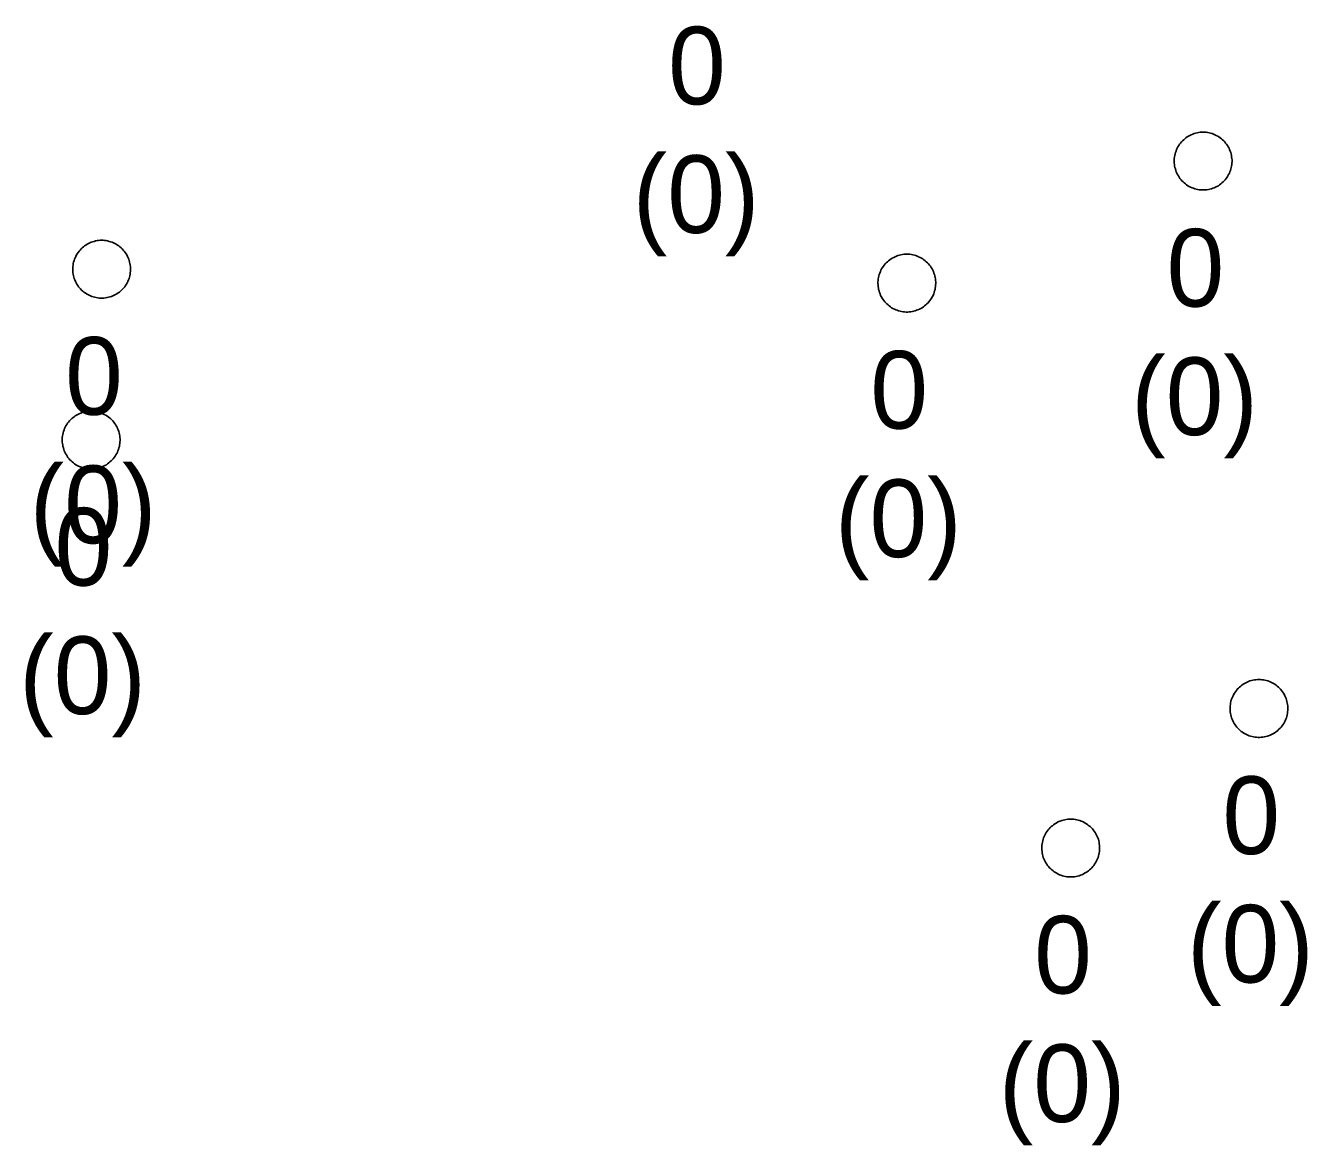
# Model space of a CAD drawing. Extents: x -606452 to -604459, y -1157823 to -1156972.
# Drawn here: x -605880.55 to -605869.47, y -1157244.86 to -1157235.18 of the extents above; entities that cross this region are included whole.
import ezdxf

# ---------------------------------------------------------------- set-up
doc = ezdxf.new("R2010")
doc.units = 0
doc.layers.add('Vstupní šachta stoky', color=7, linetype='Continuous')

msp = doc.modelspace()

# ---------------------------------------------------------------- linework, layer by layer
at = {"layer": 'Vstupní šachta stoky'}
for p, q in [((-605870.38, -1157236.102), (-605870.367, -1157236.102)), ((-605879.906, -1157237.037), (-605879.893, -1157237.037)), ((-605872.942, -1157237.157), (-605872.929, -1157237.157)), ((-605879.997, -1157238.514), (-605879.984, -1157238.514)), ((-605869.897, -1157240.835), (-605869.884, -1157240.835)), ((-605871.525, -1157242.041), (-605871.512, -1157242.041))]:
    msp.add_line(p, q, dxfattribs=at)
for points in [[(-605870.367, -1157236.102), (-605870.354, -1157236.102), (-605870.341, -1157236.103), (-605870.328, -1157236.105), (-605870.315, -1157236.108), (-605870.302, -1157236.111), (-605870.289, -1157236.114), (-605870.277, -1157236.119), (-605870.265, -1157236.124), (-605870.253, -1157236.13), (-605870.241, -1157236.136), (-605870.23, -1157236.143), (-605870.219, -1157236.151), (-605870.209, -1157236.159), (-605870.199, -1157236.167), (-605870.189, -1157236.176), (-605870.18, -1157236.186), (-605870.172, -1157236.196), (-605870.164, -1157236.207), (-605870.156, -1157236.218), (-605870.149, -1157236.229), (-605870.143, -1157236.241), (-605870.138, -1157236.253), (-605870.133, -1157236.265), (-605870.128, -1157236.277), (-605870.125, -1157236.29), (-605870.122, -1157236.303), (-605870.12, -1157236.316), (-605870.118, -1157236.329), (-605870.117, -1157236.342), (-605870.117, -1157236.355), (-605870.118, -1157236.369), (-605870.119, -1157236.382), (-605870.121, -1157236.395), (-605870.123, -1157236.408), (-605870.127, -1157236.42), (-605870.13, -1157236.433), (-605870.135, -1157236.445), (-605870.14, -1157236.458), (-605870.146, -1157236.469), (-605870.153, -1157236.481), (-605870.16, -1157236.492), (-605870.167, -1157236.503), (-605870.176, -1157236.513), (-605870.184, -1157236.523), (-605870.194, -1157236.532), (-605870.204, -1157236.541), (-605870.214, -1157236.55), (-605870.224, -1157236.557), (-605870.235, -1157236.565), (-605870.247, -1157236.571), (-605870.259, -1157236.577), (-605870.271, -1157236.583), (-605870.283, -1157236.587), (-605870.295, -1157236.592), (-605870.308, -1157236.595), (-605870.321, -1157236.598), (-605870.334, -1157236.6), (-605870.347, -1157236.601), (-605870.36, -1157236.602), (-605870.374, -1157236.602), (-605870.387, -1157236.601), (-605870.4, -1157236.6), (-605870.413, -1157236.598), (-605870.426, -1157236.595), (-605870.439, -1157236.592), (-605870.451, -1157236.587), (-605870.463, -1157236.583), (-605870.475, -1157236.577), (-605870.487, -1157236.571), (-605870.499, -1157236.565), (-605870.51, -1157236.557), (-605870.52, -1157236.55), (-605870.53, -1157236.541), (-605870.54, -1157236.532), (-605870.55, -1157236.523), (-605870.558, -1157236.513), (-605870.567, -1157236.503), (-605870.574, -1157236.492), (-605870.581, -1157236.481), (-605870.588, -1157236.469), (-605870.594, -1157236.458), (-605870.599, -1157236.445), (-605870.604, -1157236.433), (-605870.607, -1157236.42), (-605870.611, -1157236.408), (-605870.613, -1157236.395), (-605870.615, -1157236.382), (-605870.616, -1157236.369), (-605870.617, -1157236.355), (-605870.617, -1157236.342), (-605870.616, -1157236.329), (-605870.614, -1157236.316), (-605870.612, -1157236.303), (-605870.609, -1157236.29), (-605870.606, -1157236.277), (-605870.601, -1157236.265), (-605870.596, -1157236.253), (-605870.591, -1157236.241), (-605870.585, -1157236.229), (-605870.578, -1157236.218)], [(-605870.578, -1157236.218), (-605870.57, -1157236.207), (-605870.562, -1157236.196), (-605870.554, -1157236.186), (-605870.545, -1157236.176), (-605870.535, -1157236.167), (-605870.525, -1157236.159), (-605870.515, -1157236.151), (-605870.504, -1157236.143), (-605870.493, -1157236.136), (-605870.481, -1157236.13), (-605870.469, -1157236.124), (-605870.457, -1157236.119), (-605870.445, -1157236.114), (-605870.432, -1157236.111), (-605870.419, -1157236.108), (-605870.406, -1157236.105), (-605870.393, -1157236.103), (-605870.38, -1157236.102)], [(-605879.893, -1157237.037), (-605879.88, -1157237.037), (-605879.867, -1157237.038), (-605879.854, -1157237.04), (-605879.841, -1157237.043), (-605879.828, -1157237.046), (-605879.815, -1157237.049), (-605879.803, -1157237.054), (-605879.791, -1157237.059), (-605879.779, -1157237.065), (-605879.767, -1157237.071), (-605879.756, -1157237.078), (-605879.745, -1157237.086), (-605879.735, -1157237.094), (-605879.725, -1157237.102), (-605879.715, -1157237.111), (-605879.706, -1157237.121), (-605879.698, -1157237.131), (-605879.69, -1157237.142), (-605879.682, -1157237.153), (-605879.675, -1157237.164), (-605879.669, -1157237.176), (-605879.664, -1157237.188), (-605879.659, -1157237.2), (-605879.654, -1157237.212), (-605879.651, -1157237.225), (-605879.648, -1157237.238), (-605879.646, -1157237.251), (-605879.644, -1157237.264), (-605879.643, -1157237.277), (-605879.643, -1157237.29), (-605879.644, -1157237.304), (-605879.645, -1157237.317), (-605879.647, -1157237.33), (-605879.649, -1157237.343), (-605879.653, -1157237.355), (-605879.656, -1157237.368), (-605879.661, -1157237.38), (-605879.666, -1157237.393), (-605879.672, -1157237.404), (-605879.679, -1157237.416), (-605879.686, -1157237.427), (-605879.693, -1157237.438), (-605879.702, -1157237.448), (-605879.71, -1157237.458), (-605879.72, -1157237.467), (-605879.73, -1157237.476), (-605879.74, -1157237.485), (-605879.75, -1157237.492), (-605879.761, -1157237.5), (-605879.773, -1157237.506), (-605879.785, -1157237.512), (-605879.797, -1157237.518), (-605879.809, -1157237.522), (-605879.821, -1157237.527), (-605879.834, -1157237.53), (-605879.847, -1157237.533), (-605879.86, -1157237.535), (-605879.873, -1157237.536), (-605879.886, -1157237.537), (-605879.9, -1157237.537), (-605879.913, -1157237.536), (-605879.926, -1157237.535), (-605879.939, -1157237.533), (-605879.952, -1157237.53), (-605879.965, -1157237.527), (-605879.977, -1157237.522), (-605879.989, -1157237.518), (-605880.001, -1157237.512), (-605880.013, -1157237.506), (-605880.025, -1157237.5), (-605880.036, -1157237.492), (-605880.046, -1157237.485), (-605880.056, -1157237.476), (-605880.066, -1157237.467), (-605880.076, -1157237.458), (-605880.084, -1157237.448), (-605880.093, -1157237.438), (-605880.1, -1157237.427), (-605880.107, -1157237.416), (-605880.114, -1157237.404), (-605880.12, -1157237.393), (-605880.125, -1157237.38), (-605880.13, -1157237.368), (-605880.133, -1157237.355), (-605880.137, -1157237.343), (-605880.139, -1157237.33), (-605880.141, -1157237.317), (-605880.142, -1157237.304), (-605880.143, -1157237.29), (-605880.143, -1157237.277), (-605880.142, -1157237.264), (-605880.14, -1157237.251), (-605880.138, -1157237.238), (-605880.135, -1157237.225), (-605880.132, -1157237.212), (-605880.127, -1157237.2), (-605880.122, -1157237.188), (-605880.117, -1157237.176), (-605880.111, -1157237.164), (-605880.104, -1157237.153)], [(-605880.104, -1157237.153), (-605880.096, -1157237.142), (-605880.088, -1157237.131), (-605880.08, -1157237.121), (-605880.071, -1157237.111), (-605880.061, -1157237.102), (-605880.051, -1157237.094), (-605880.041, -1157237.086), (-605880.03, -1157237.078), (-605880.019, -1157237.071), (-605880.007, -1157237.065), (-605879.995, -1157237.059), (-605879.983, -1157237.054), (-605879.971, -1157237.049), (-605879.958, -1157237.046), (-605879.945, -1157237.043), (-605879.932, -1157237.04), (-605879.919, -1157237.038), (-605879.906, -1157237.037)], [(-605872.929, -1157237.157), (-605872.916, -1157237.157), (-605872.903, -1157237.158), (-605872.89, -1157237.16), (-605872.877, -1157237.163), (-605872.864, -1157237.166), (-605872.851, -1157237.169), (-605872.839, -1157237.174), (-605872.827, -1157237.179), (-605872.815, -1157237.185), (-605872.803, -1157237.191), (-605872.792, -1157237.198), (-605872.781, -1157237.206), (-605872.771, -1157237.214), (-605872.761, -1157237.222), (-605872.751, -1157237.231), (-605872.742, -1157237.241), (-605872.734, -1157237.251), (-605872.726, -1157237.262), (-605872.718, -1157237.273), (-605872.711, -1157237.284), (-605872.705, -1157237.296), (-605872.7, -1157237.308), (-605872.695, -1157237.32), (-605872.69, -1157237.332), (-605872.687, -1157237.345), (-605872.684, -1157237.358), (-605872.682, -1157237.371), (-605872.68, -1157237.384), (-605872.679, -1157237.397), (-605872.679, -1157237.41), (-605872.68, -1157237.424), (-605872.681, -1157237.437), (-605872.683, -1157237.45), (-605872.685, -1157237.463), (-605872.689, -1157237.475), (-605872.692, -1157237.488), (-605872.697, -1157237.5), (-605872.702, -1157237.513), (-605872.708, -1157237.524), (-605872.715, -1157237.536), (-605872.722, -1157237.547), (-605872.729, -1157237.558), (-605872.738, -1157237.568), (-605872.746, -1157237.578), (-605872.756, -1157237.587), (-605872.766, -1157237.596), (-605872.776, -1157237.605), (-605872.786, -1157237.612), (-605872.797, -1157237.62), (-605872.809, -1157237.626), (-605872.821, -1157237.632), (-605872.833, -1157237.638), (-605872.845, -1157237.642), (-605872.857, -1157237.647), (-605872.87, -1157237.65), (-605872.883, -1157237.653), (-605872.896, -1157237.655), (-605872.909, -1157237.656), (-605872.922, -1157237.657), (-605872.936, -1157237.657), (-605872.949, -1157237.656), (-605872.962, -1157237.655), (-605872.975, -1157237.653), (-605872.988, -1157237.65), (-605873.001, -1157237.647), (-605873.013, -1157237.642), (-605873.025, -1157237.638), (-605873.037, -1157237.632), (-605873.049, -1157237.626), (-605873.061, -1157237.62), (-605873.072, -1157237.612), (-605873.082, -1157237.605), (-605873.092, -1157237.596), (-605873.102, -1157237.587), (-605873.112, -1157237.578), (-605873.12, -1157237.568), (-605873.129, -1157237.558), (-605873.136, -1157237.547), (-605873.143, -1157237.536), (-605873.15, -1157237.524), (-605873.156, -1157237.513), (-605873.161, -1157237.5), (-605873.166, -1157237.488), (-605873.169, -1157237.475), (-605873.173, -1157237.463), (-605873.175, -1157237.45), (-605873.177, -1157237.437), (-605873.178, -1157237.424), (-605873.179, -1157237.41), (-605873.179, -1157237.397), (-605873.178, -1157237.384), (-605873.176, -1157237.371), (-605873.174, -1157237.358), (-605873.171, -1157237.345), (-605873.168, -1157237.332), (-605873.163, -1157237.32), (-605873.158, -1157237.308), (-605873.153, -1157237.296), (-605873.147, -1157237.284), (-605873.14, -1157237.273)], [(-605873.14, -1157237.273), (-605873.132, -1157237.262), (-605873.124, -1157237.251), (-605873.116, -1157237.241), (-605873.107, -1157237.231), (-605873.097, -1157237.222), (-605873.087, -1157237.214), (-605873.077, -1157237.206), (-605873.066, -1157237.198), (-605873.055, -1157237.191), (-605873.043, -1157237.185), (-605873.031, -1157237.179), (-605873.019, -1157237.174), (-605873.007, -1157237.169), (-605872.994, -1157237.166), (-605872.981, -1157237.163), (-605872.968, -1157237.16), (-605872.955, -1157237.158), (-605872.942, -1157237.157)], [(-605879.984, -1157238.514), (-605879.971, -1157238.514), (-605879.958, -1157238.515), (-605879.945, -1157238.517), (-605879.932, -1157238.52), (-605879.919, -1157238.523), (-605879.906, -1157238.526), (-605879.894, -1157238.531), (-605879.882, -1157238.536), (-605879.87, -1157238.542), (-605879.858, -1157238.548), (-605879.847, -1157238.555), (-605879.836, -1157238.563), (-605879.826, -1157238.571), (-605879.816, -1157238.579), (-605879.806, -1157238.588), (-605879.797, -1157238.598), (-605879.789, -1157238.608), (-605879.781, -1157238.619), (-605879.773, -1157238.63), (-605879.766, -1157238.641), (-605879.76, -1157238.653), (-605879.755, -1157238.665), (-605879.75, -1157238.677), (-605879.745, -1157238.689), (-605879.742, -1157238.702), (-605879.739, -1157238.715), (-605879.737, -1157238.728), (-605879.735, -1157238.741), (-605879.734, -1157238.754), (-605879.734, -1157238.767), (-605879.735, -1157238.781), (-605879.736, -1157238.794), (-605879.738, -1157238.807), (-605879.74, -1157238.82), (-605879.744, -1157238.832), (-605879.747, -1157238.845), (-605879.752, -1157238.857), (-605879.757, -1157238.87), (-605879.763, -1157238.881), (-605879.77, -1157238.893), (-605879.777, -1157238.904), (-605879.784, -1157238.915), (-605879.793, -1157238.925), (-605879.801, -1157238.935), (-605879.811, -1157238.944), (-605879.821, -1157238.953), (-605879.831, -1157238.962), (-605879.841, -1157238.969), (-605879.852, -1157238.977), (-605879.864, -1157238.983), (-605879.876, -1157238.989), (-605879.888, -1157238.995), (-605879.9, -1157238.999), (-605879.912, -1157239.004), (-605879.925, -1157239.007), (-605879.938, -1157239.01), (-605879.951, -1157239.012), (-605879.964, -1157239.013), (-605879.977, -1157239.014), (-605879.991, -1157239.014), (-605880.004, -1157239.013), (-605880.017, -1157239.012), (-605880.03, -1157239.01), (-605880.043, -1157239.007), (-605880.056, -1157239.004), (-605880.068, -1157238.999), (-605880.08, -1157238.995), (-605880.092, -1157238.989), (-605880.104, -1157238.983), (-605880.116, -1157238.977), (-605880.127, -1157238.969), (-605880.137, -1157238.962), (-605880.147, -1157238.953), (-605880.157, -1157238.944), (-605880.167, -1157238.935), (-605880.175, -1157238.925), (-605880.184, -1157238.915), (-605880.191, -1157238.904), (-605880.198, -1157238.893), (-605880.205, -1157238.881), (-605880.211, -1157238.87), (-605880.216, -1157238.857), (-605880.221, -1157238.845), (-605880.224, -1157238.832), (-605880.228, -1157238.82), (-605880.23, -1157238.807), (-605880.232, -1157238.794), (-605880.233, -1157238.781), (-605880.234, -1157238.767), (-605880.234, -1157238.754), (-605880.233, -1157238.741), (-605880.231, -1157238.728), (-605880.229, -1157238.715), (-605880.226, -1157238.702), (-605880.223, -1157238.689), (-605880.218, -1157238.677), (-605880.213, -1157238.665), (-605880.208, -1157238.653), (-605880.202, -1157238.641), (-605880.195, -1157238.63)], [(-605880.195, -1157238.63), (-605880.187, -1157238.619), (-605880.179, -1157238.608), (-605880.171, -1157238.598), (-605880.162, -1157238.588), (-605880.152, -1157238.579), (-605880.142, -1157238.571), (-605880.132, -1157238.563), (-605880.121, -1157238.555), (-605880.11, -1157238.548), (-605880.098, -1157238.542), (-605880.086, -1157238.536), (-605880.074, -1157238.531), (-605880.062, -1157238.526), (-605880.049, -1157238.523), (-605880.036, -1157238.52), (-605880.023, -1157238.517), (-605880.01, -1157238.515), (-605879.997, -1157238.514)], [(-605869.884, -1157240.835), (-605869.871, -1157240.835), (-605869.858, -1157240.836), (-605869.845, -1157240.838), (-605869.832, -1157240.841), (-605869.819, -1157240.844), (-605869.806, -1157240.847), (-605869.794, -1157240.852), (-605869.782, -1157240.857), (-605869.77, -1157240.863), (-605869.758, -1157240.869), (-605869.747, -1157240.876), (-605869.736, -1157240.884), (-605869.726, -1157240.892), (-605869.716, -1157240.9), (-605869.706, -1157240.909), (-605869.697, -1157240.919), (-605869.689, -1157240.929), (-605869.681, -1157240.94), (-605869.673, -1157240.951), (-605869.666, -1157240.962), (-605869.66, -1157240.974), (-605869.655, -1157240.986), (-605869.65, -1157240.998), (-605869.645, -1157241.01), (-605869.642, -1157241.023), (-605869.639, -1157241.036), (-605869.637, -1157241.049), (-605869.635, -1157241.062), (-605869.634, -1157241.075), (-605869.634, -1157241.088), (-605869.635, -1157241.102), (-605869.636, -1157241.115), (-605869.638, -1157241.128), (-605869.64, -1157241.141), (-605869.644, -1157241.153), (-605869.647, -1157241.166), (-605869.652, -1157241.178), (-605869.657, -1157241.191), (-605869.663, -1157241.202), (-605869.67, -1157241.214), (-605869.677, -1157241.225), (-605869.684, -1157241.236), (-605869.693, -1157241.246), (-605869.701, -1157241.256), (-605869.711, -1157241.265), (-605869.721, -1157241.274), (-605869.731, -1157241.283), (-605869.741, -1157241.29), (-605869.752, -1157241.298), (-605869.764, -1157241.304), (-605869.776, -1157241.31), (-605869.788, -1157241.316), (-605869.8, -1157241.32), (-605869.812, -1157241.325), (-605869.825, -1157241.328), (-605869.838, -1157241.331), (-605869.851, -1157241.333), (-605869.864, -1157241.334), (-605869.877, -1157241.335), (-605869.891, -1157241.335), (-605869.904, -1157241.334), (-605869.917, -1157241.333), (-605869.93, -1157241.331), (-605869.943, -1157241.328), (-605869.956, -1157241.325), (-605869.968, -1157241.32), (-605869.98, -1157241.316), (-605869.992, -1157241.31), (-605870.004, -1157241.304), (-605870.016, -1157241.298), (-605870.027, -1157241.29), (-605870.037, -1157241.283), (-605870.047, -1157241.274), (-605870.057, -1157241.265), (-605870.067, -1157241.256), (-605870.075, -1157241.246), (-605870.084, -1157241.236), (-605870.091, -1157241.225), (-605870.098, -1157241.214), (-605870.105, -1157241.202), (-605870.111, -1157241.191), (-605870.116, -1157241.178), (-605870.121, -1157241.166), (-605870.124, -1157241.153), (-605870.128, -1157241.141), (-605870.13, -1157241.128), (-605870.132, -1157241.115), (-605870.133, -1157241.102), (-605870.134, -1157241.088), (-605870.134, -1157241.075), (-605870.133, -1157241.062), (-605870.131, -1157241.049), (-605870.129, -1157241.036), (-605870.126, -1157241.023), (-605870.123, -1157241.01), (-605870.118, -1157240.998), (-605870.113, -1157240.986), (-605870.108, -1157240.974), (-605870.102, -1157240.962), (-605870.095, -1157240.951)], [(-605870.095, -1157240.951), (-605870.087, -1157240.94), (-605870.079, -1157240.929), (-605870.071, -1157240.919), (-605870.062, -1157240.909), (-605870.052, -1157240.9), (-605870.042, -1157240.892), (-605870.032, -1157240.884), (-605870.021, -1157240.876), (-605870.01, -1157240.869), (-605869.998, -1157240.863), (-605869.986, -1157240.857), (-605869.974, -1157240.852), (-605869.962, -1157240.847), (-605869.949, -1157240.844), (-605869.936, -1157240.841), (-605869.923, -1157240.838), (-605869.91, -1157240.836), (-605869.897, -1157240.835)], [(-605871.512, -1157242.041), (-605871.499, -1157242.041), (-605871.486, -1157242.042), (-605871.473, -1157242.044), (-605871.46, -1157242.047), (-605871.447, -1157242.05), (-605871.434, -1157242.053), (-605871.422, -1157242.058), (-605871.41, -1157242.063), (-605871.398, -1157242.069), (-605871.386, -1157242.075), (-605871.375, -1157242.082), (-605871.364, -1157242.09), (-605871.354, -1157242.098), (-605871.344, -1157242.106), (-605871.334, -1157242.115), (-605871.325, -1157242.125), (-605871.317, -1157242.135), (-605871.309, -1157242.146), (-605871.301, -1157242.157), (-605871.294, -1157242.168), (-605871.288, -1157242.18), (-605871.283, -1157242.192), (-605871.278, -1157242.204), (-605871.273, -1157242.216), (-605871.27, -1157242.229), (-605871.267, -1157242.242), (-605871.265, -1157242.255), (-605871.263, -1157242.268), (-605871.262, -1157242.281), (-605871.262, -1157242.294), (-605871.263, -1157242.308), (-605871.264, -1157242.321), (-605871.266, -1157242.334), (-605871.268, -1157242.347), (-605871.272, -1157242.359), (-605871.275, -1157242.372), (-605871.28, -1157242.384), (-605871.285, -1157242.397), (-605871.291, -1157242.408), (-605871.298, -1157242.42), (-605871.305, -1157242.431), (-605871.312, -1157242.442), (-605871.321, -1157242.452), (-605871.329, -1157242.462), (-605871.339, -1157242.471), (-605871.349, -1157242.48), (-605871.359, -1157242.489), (-605871.369, -1157242.496), (-605871.38, -1157242.504), (-605871.392, -1157242.51), (-605871.404, -1157242.516), (-605871.416, -1157242.522), (-605871.428, -1157242.526), (-605871.44, -1157242.531), (-605871.453, -1157242.534), (-605871.466, -1157242.537), (-605871.479, -1157242.539), (-605871.492, -1157242.54), (-605871.505, -1157242.541), (-605871.519, -1157242.541), (-605871.532, -1157242.54), (-605871.545, -1157242.539), (-605871.558, -1157242.537), (-605871.571, -1157242.534), (-605871.584, -1157242.531), (-605871.596, -1157242.526), (-605871.608, -1157242.522), (-605871.62, -1157242.516), (-605871.632, -1157242.51), (-605871.644, -1157242.504), (-605871.655, -1157242.496), (-605871.665, -1157242.489), (-605871.675, -1157242.48), (-605871.685, -1157242.471), (-605871.695, -1157242.462), (-605871.703, -1157242.452), (-605871.712, -1157242.442), (-605871.719, -1157242.431), (-605871.726, -1157242.42), (-605871.733, -1157242.408), (-605871.739, -1157242.397), (-605871.744, -1157242.384), (-605871.749, -1157242.372), (-605871.752, -1157242.359), (-605871.756, -1157242.347), (-605871.758, -1157242.334), (-605871.76, -1157242.321), (-605871.761, -1157242.308), (-605871.762, -1157242.294), (-605871.762, -1157242.281), (-605871.761, -1157242.268), (-605871.759, -1157242.255), (-605871.757, -1157242.242), (-605871.754, -1157242.229), (-605871.751, -1157242.216), (-605871.746, -1157242.204), (-605871.741, -1157242.192), (-605871.736, -1157242.18), (-605871.73, -1157242.168), (-605871.723, -1157242.157)], [(-605871.723, -1157242.157), (-605871.715, -1157242.146), (-605871.707, -1157242.135), (-605871.699, -1157242.125), (-605871.69, -1157242.115), (-605871.68, -1157242.106), (-605871.67, -1157242.098), (-605871.66, -1157242.09), (-605871.649, -1157242.082), (-605871.638, -1157242.075), (-605871.626, -1157242.069), (-605871.614, -1157242.063), (-605871.602, -1157242.058), (-605871.59, -1157242.053), (-605871.577, -1157242.05), (-605871.564, -1157242.047), (-605871.551, -1157242.044), (-605871.538, -1157242.042), (-605871.525, -1157242.041)]]:
    msp.add_lwpolyline(points, dxfattribs=at)

# ---------------------------------------------------------------- texts
for s, height, p in [('0', 0.671, (-605874.994, -1157235.862)), ('(0)', 0.6708, (-605875.3, -1157236.973)), ('0', 0.671, (-605870.683, -1157237.61)), ('0', 0.671, (-605880.209, -1157238.545)), ('0', 0.671, (-605873.245, -1157238.665)), ('(0)', 0.6708, (-605870.989, -1157238.721)), ('(0)', 0.6708, (-605880.515, -1157239.656)), ('(0)', 0.6708, (-605873.551, -1157239.776)), ('0', 0.671, (-605880.3, -1157240.022)), ('(0)', 0.6708, (-605880.606, -1157241.133)), ('0', 0.671, (-605870.2, -1157242.343)), ('(0)', 0.6708, (-605870.506, -1157243.454)), ('0', 0.671, (-605871.828, -1157243.549)), ('(0)', 0.6708, (-605872.134, -1157244.66))]:
    msp.add_text(s, height=height, dxfattribs=at).set_placement(p)

doc.saveas('drawing.dxf')
